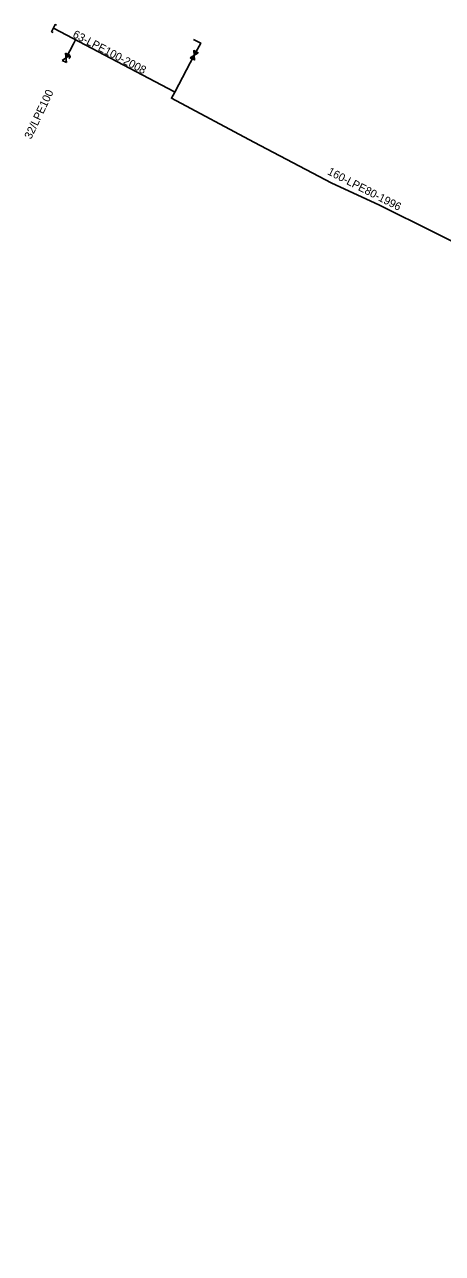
# Model space of a CAD drawing. Extents: x -741323 to -735641, y -1146295 to -1143223.
# Drawn here: x -737079.6 to -737027.3, y -1144930.2 to -1144776.7 of the extents above; entities that cross this region are included whole.
import ezdxf

# ---------------------------------------------------------------- set-up
doc = ezdxf.new("R2010")
doc.units = 0
for name, color, linetype in [('Vrstva 1', 7, 'Continuous'), ('Vrstva 21', 7, 'Continuous'), ('Vrstva 22', 7, 'Continuous'), ('Vrstva 31', 7, 'Continuous'), ('Vrstva 32', 7, 'Continuous')]:
    doc.layers.add(name, color=color, linetype=linetype)

# ---------------------------------------------------------------- blocks, each defined once
blk = doc.blocks.new('DEC063-SN')
at = {"layer": 'Vrstva 1'}
for p, q in [((-0.5, -0.3), (0.5, 0.3)), ((0.5, -0.3), (-0.5, 0.3)), ((-0.5, 0.3), (-0.5, -0.3)), ((0.5, 0.3), (0.5, -0.3)), ((0.126, -0.318), (0.126, -0.458)), ((0.126, -0.384), (0.206, -0.384)), ((0.206, -0.458), (0.206, -0.318)), ((0.366, -0.458), (0.366, -0.318))]:
    blk.add_line(p, q, dxfattribs=at)
for points in [[(0.246, -0.318), (0.246, -0.418), (0.252, -0.438), (0.264, -0.451), (0.281, -0.458), (0.292, -0.458), (0.309, -0.451), (0.321, -0.438), (0.326, -0.418), (0.326, -0.318)], [(0.366, -0.318), (0.418, -0.318), (0.435, -0.325), (0.441, -0.331), (0.446, -0.344), (0.446, -0.364), (0.441, -0.378), (0.435, -0.384), (0.418, -0.391), (0.366, -0.391)]]:
    blk.add_lwpolyline(points, dxfattribs=at)
blk = doc.blocks.new('DEC130')
at = {"layer": 'Vrstva 1'}
blk.add_lwpolyline([(0.2, 0.5), (0, 0.5), (0, -0.5), (0.2, -0.5)], dxfattribs=at)
blk = doc.blocks.new('DEC124')
at = {"layer": 'Vrstva 1'}
blk.add_lwpolyline([(-0.5, 0.3), (0.5, -0.3), (0.5, 0.3), (-0.5, -0.3), (-0.5, 0.3)], dxfattribs=at)

msp = doc.modelspace()

# ---------------------------------------------------------------- linework, layer by layer
at = {"layer": 'Vrstva 21'}
for points in [[(-737060.82, -1144785.09), (-737075.97, -1144777.13)], [(-737058.36, -1144780.51), (-737057.53, -1144779), (-737058.45, -1144778.56)], [(-737060.79, -1144785.11), (-737058.36, -1144780.51)], [(-736837.74, -1144930.19), (-736842.64, -1144929.16), (-736858.24, -1144923.64), (-736868.79, -1144919.27), (-736876.33, -1144916.09), (-736886.91, -1144910.92), (-736896.95, -1144904.39), (-736905.44, -1144897.4), (-736914.24, -1144888.14), (-736923.27, -1144880.26), (-736945.82, -1144863.87), (-736963.47, -1144849.65), (-736972.49, -1144841.68), (-736998.17, -1144820.03), (-737011.65, -1144812.02), (-737021.15, -1144806.2), (-737035.24, -1144799.21), (-737041.14, -1144796.5), (-737050.9, -1144791.38), (-737061.2, -1144785.89), (-737060.79, -1144785.11)]]:
    msp.add_lwpolyline(points, dxfattribs=at)
at = {"layer": 'Vrstva 31'}
msp.add_lwpolyline([(-737073.22, -1144778.58), (-737073.47, -1144779.09), (-737074.39, -1144780.84)], dxfattribs=at)

# ---------------------------------------------------------------- block references
at = {"layer": 'Vrstva 22'}
for name, p, rotation in [('DEC130', (-737075.97, -1144777.13), -25.900357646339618), ('DEC124', (-737058.36, -1144780.51), 63.95818344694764)]:
    msp.add_blockref(name, p, dxfattribs=dict(at, rotation=rotation))
at = {"layer": 'Vrstva 32', "rotation": 66.03751097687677}
msp.add_blockref('DEC063-SN', (-737074.39, -1144780.84), dxfattribs=at)

# ---------------------------------------------------------------- texts
at = {"layer": 'Vrstva 21'}
for s, rotation, p in [('63-LPE100-2008', 332.275, (-737073.64, -1144778.2)), ('160-LPE80-1996', 332.787, (-737041.77, -1144795.35))]:
    msp.add_text(s, height=1, rotation=rotation, dxfattribs=at).set_placement(p)
at = {"layer": 'Vrstva 31'}
msp.add_text('32/LPE100', height=1, rotation=64.563, dxfattribs=at).set_placement((-737078.76, -1144791.08))

doc.saveas('drawing.dxf')
